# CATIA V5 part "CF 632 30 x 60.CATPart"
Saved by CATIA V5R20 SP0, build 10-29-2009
Part number: CF 632 30 x 60
Definition: NONE
Nomenclature: CF 632 30 x 60
Source: Unknown
Description: CF 632 30 x 60
Bounding box of the stored display mesh (mm): x -13 to 47, y -26.5 to 26.5, z -26.5 to 26.5
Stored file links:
  C:\Users\Utente\Desktop\IO LAVORO\3D X SITO CF\X SITO\CF 632\CF 632 30 x 60.CATPart
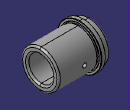
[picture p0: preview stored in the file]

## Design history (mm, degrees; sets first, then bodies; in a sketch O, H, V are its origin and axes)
Body1 "CF 632 30 x 60" (main body)
  Solid1: solid without history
